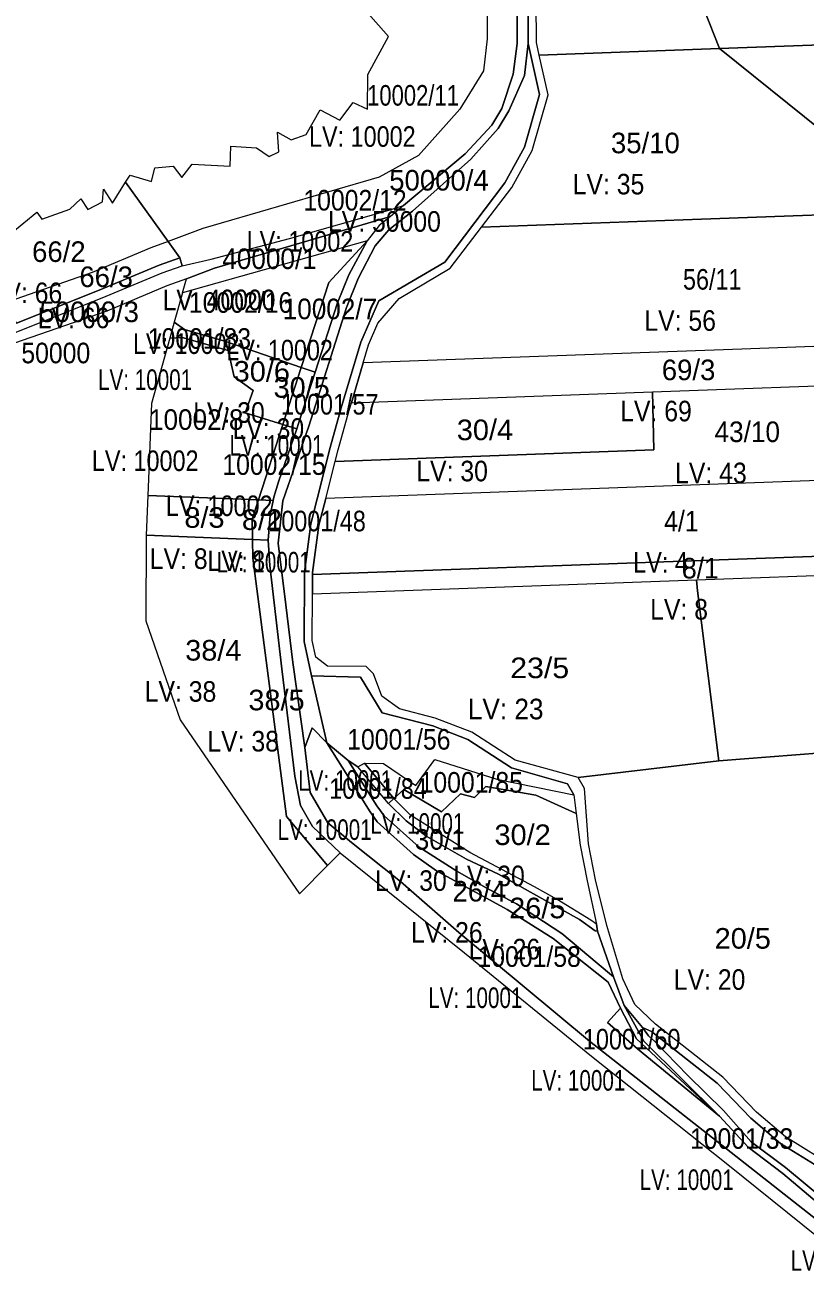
# Model space of a CAD drawing. Extents: x -713758 to -711119, y -1123067 to -1120789.
# Drawn here: x -713169 to -712790, y -1122550 to -1121945 of the extents above; entities that cross this region are included whole.
import ezdxf
from ezdxf.enums import TextEntityAlignment as Align

# ---------------------------------------------------------------- set-up
doc = ezdxf.new("R2010")
doc.units = 0
doc.header["$LTSCALE"] = 4
doc.layers.add('10', color=7, linetype='Continuous', lineweight=13)
doc.layers.add('11', color=7, linetype='Continuous')
doc.layers.add('13', color=7, linetype='Continuous')

msp = doc.modelspace()

# ---------------------------------------------------------------- linework, layer by layer
at = {"layer": '10'}
for points in [[(-712944.91, -1121832.77), (-712944, -1121951.73), (-712945.8, -1121967.3), (-712957.4, -1121986.04), (-712977.36, -1122008.49), (-712996.6, -1122018.99), (-713045.48, -1122033.25), (-713082.19, -1122044), (-713099.09, -1122050.28), (-713119.7, -1122021.46), (-713117.55, -1122018), (-713107.1, -1122021.15), (-713105.44, -1122014.52), (-713096.64, -1122013.69), (-713092.33, -1122019.16), (-713087.35, -1122012.69), (-713068.94, -1122013.69), (-713068.61, -1122003.9), (-713056.16, -1122004.73), (-713050.03, -1122009.04), (-713045.22, -1122006.72), (-713045.88, -1121997.1), (-713039.36, -1122000.91), (-713031.99, -1121998.26), (-713025.14, -1121986.31), (-713015.68, -1121991.29), (-713009.21, -1121982.66), (-713002.25, -1121985.98), (-713002.08, -1121969.06), (-712991.96, -1121950.64), (-713003.08, -1121938.2)], [(-712929.21, -1121894.95), (-712929.46, -1121954.09), (-712931.35, -1121968.92), (-712936.86, -1121985.6), (-712941.79, -1121993.69), (-712954.71, -1122007.7), (-712984.65, -1122032.69), (-712991, -1122038.19), (-712996.49, -1122042.47), (-713002.32, -1122049.96), (-713011.31, -1122066.5), (-713016.78, -1122080.08), (-713027.64, -1122113.79), (-713035.65, -1122138.64), (-713036.53, -1122141.22), (-713045.38, -1122167.06), (-713047.67, -1122174.42), (-713048.02, -1122176.08), (-713049.5, -1122183.21), (-713050.51, -1122195.35), (-713049.59, -1122207.7), (-713043.87, -1122257.93), (-713037.46, -1122309.99), (-713034.78, -1122324.24), (-713028.91, -1122334.48), (-713015.4, -1122347.26), (-712955.02, -1122395.77), (-712893.31, -1122446.1), (-712827.18, -1122498.66), (-712776.53, -1122539.37)], [(-712772.56, -1122534.45), (-712894.29, -1122438.71), (-712957.76, -1122385.97), (-712986.1, -1122361.18), (-713010.04, -1122342.27), (-713021.42, -1122332.63), (-713029.98, -1122317.89), (-713032.71, -1122296.02), (-713038.55, -1122254.75), (-713041.88, -1122226.75), (-713045.67, -1122196.79), (-713043.32, -1122176.31), (-713030.64, -1122139.91), (-713012.41, -1122082.34), (-713006.74, -1122068.22), (-712998.53, -1122052.43), (-712991.77, -1122044.64), (-712980.32, -1122035.6), (-712951.96, -1122010.31), (-712938.67, -1121995.31), (-712933.46, -1121986.71), (-712925.93, -1121969.6), (-712924.13, -1121954.03), (-712924.19, -1121934.01)], [(-712924.19, -1121934.01), (-712924.13, -1121954.03), (-712918.57, -1121978.84), (-712925.98, -1122004.5), (-712935.4, -1122021.81), (-712964.66, -1122060.23), (-712996.72, -1122079.08), (-713005.42, -1122099.09), (-713014.94, -1122131.09), (-713020.31, -1122150.38), (-713029.69, -1122187.36), (-713032.85, -1122210.83), (-713033.03, -1122244.52)], [(-712774.62, -1122500.39), (-712799.12, -1122485.22), (-712813.16, -1122473.21), (-712829.61, -1122456.21), (-712862.21, -1122430.51), (-712872.38, -1122420.97), (-712878.07, -1122408.41), (-712885.9, -1122382.52), (-712891.47, -1122360.38), (-712894.85, -1122342.83), (-712896.75, -1122315.98), (-712899.9, -1122310.71), (-712930.52, -1122302.24), (-712951.57, -1122288.64), (-712969.26, -1122281.82), (-712986.71, -1122277.24), (-712995.2, -1122271.13), (-712999.26, -1122260.23), (-713002.77, -1122256.8), (-713021.65, -1122256.64), (-713027.24, -1122252.26), (-713029.03, -1122244.1), (-713028.91, -1122221.35), (-713028.86, -1122212.11), (-713028.85, -1122211.11), (-713025.76, -1122188.12), (-713022.45, -1122175.1), (-713017.89, -1122157.12), (-713016.44, -1122151.41), (-713011.1, -1122132.22), (-713010.04, -1122128.66), (-713004.26, -1122109.23), (-713001.65, -1122100.46), (-712997.1, -1122089.99), (-712986.87, -1122077.93), (-712961.95, -1122063.28), (-712946.78, -1122043.35), (-712932.04, -1122023.99), (-712922.26, -1122006.03), (-712914.44, -1121978.97), (-712918.75, -1121959.74), (-712920.13, -1121953.58), (-712920.19, -1121933.95)], [(-713179.85, -1122097.09), (-713131.11, -1122077.56), (-713102.01, -1122065.46), (-713092.2, -1122062.07), (-713078.09, -1122058.85), (-713040.02, -1122048.87), (-712992.26, -1122035.27), (-712984.65, -1122032.69), (-712991, -1122038.19), (-713039.52, -1122052.34), (-713076.57, -1122063.19), (-713090.12, -1122068.35), (-713099.67, -1122071.82), (-713128.83, -1122084.07), (-713177.94, -1122101.13)], [(-713179.85, -1122097.09), (-713131.11, -1122077.56), (-713102.01, -1122065.46), (-713092.2, -1122062.07), (-713093.3, -1122058.22), (-713103.43, -1122061.72), (-713132.6, -1122073.85), (-713172.8, -1122089.95)], [(-713033.03, -1122244.52), (-713029.35, -1122261.3), (-713005.54, -1122261.94), (-712995.14, -1122279.16), (-712970.49, -1122285.63), (-712953.4, -1122292.22), (-712932.2, -1122305.92), (-712905.05, -1122313.79), (-712901.9, -1122319.06), (-712900.74, -1122328.21), (-712898.8, -1122343.47), (-712895.46, -1122360.8), (-712890.97, -1122381.84), (-712890.37, -1122385.34), (-712882.72, -1122407.47), (-712877.48, -1122421.44), (-712868.55, -1122432.16), (-712864.27, -1122433.98), (-712832.3, -1122459.19), (-712815.9, -1122476.13), (-712801.49, -1122488.46), (-712776.27, -1122504.07)], [(-712782.82, -1122518), (-712800.46, -1122503.04), (-712817.28, -1122490.23), (-712831.24, -1122475.24), (-712870.99, -1122442.45), (-712885.59, -1122429.63), (-712879.25, -1122422.78), (-712885.31, -1122410.06), (-712911.93, -1122388.85), (-712934.36, -1122374.71), (-712947.93, -1122367.31), (-712968.65, -1122355.94), (-712979.85, -1122348.12), (-712997.42, -1122332.12), (-713001.17, -1122326.78), (-713009.01, -1122314.38), (-713022.03, -1122293.87), (-713029.08, -1122286.58), (-713032.71, -1122296.02), (-713029.98, -1122317.89), (-713021.42, -1122332.63), (-713010.04, -1122342.27), (-712986.1, -1122361.18), (-712957.76, -1122385.97), (-712894.29, -1122438.71), (-712772.56, -1122534.45)], [(-712776.27, -1122504.07), (-712801.49, -1122488.46), (-712815.9, -1122476.13), (-712832.3, -1122459.19), (-712864.27, -1122433.98), (-712868.55, -1122432.16), (-712865.73, -1122436.15), (-712862.65, -1122438.97), (-712846.59, -1122455.35), (-712829.18, -1122472.48), (-712815.86, -1122487.57), (-712799.18, -1122500.14), (-712780.93, -1122515.2)]]:
    msp.add_lwpolyline(points, dxfattribs=at)
for points in [[(-713099.09, -1122050.28), (-713093.3, -1122058.22), (-713092.2, -1122062.07), (-713078.09, -1122058.85), (-713040.02, -1122048.87), (-712992.26, -1122035.27), (-712984.65, -1122032.69), (-712954.71, -1122007.7), (-712941.79, -1121993.69), (-712936.86, -1121985.6), (-712931.35, -1121968.92), (-712929.46, -1121954.09), (-712929.21, -1121894.95), (-712929.12, -1121844.01), (-712939.8, -1121834.06), (-712944.91, -1121832.77), (-712944, -1121951.73), (-712945.8, -1121967.3), (-712957.4, -1121986.04), (-712977.36, -1122008.49), (-712996.6, -1122018.99), (-713045.48, -1122033.25), (-713082.19, -1122044)], [(-712870.42, -1121857.05), (-712700.85, -1121850.86), (-712698.93, -1121864.01), (-712694.13, -1121895.03), (-712687.55, -1121951.31), (-712831.1, -1121956.54)], [(-712920.74, -1121858.89), (-712870.42, -1121857.05), (-712831.1, -1121956.54), (-712918.75, -1121959.74), (-712920.13, -1121953.58), (-712920.19, -1121933.95), (-712920.62, -1121894.76)], [(-713045.67, -1122196.79), (-713041.88, -1122226.75), (-713038.55, -1122254.75), (-713032.71, -1122296.02), (-713029.08, -1122286.58), (-713022.03, -1122293.87), (-713029.35, -1122261.3), (-713033.03, -1122244.52), (-713032.85, -1122210.83), (-713029.69, -1122187.36), (-713020.31, -1122150.38), (-713014.94, -1122131.09), (-713005.42, -1122099.09), (-712996.72, -1122079.08), (-712964.66, -1122060.23), (-712935.4, -1122021.81), (-712925.98, -1122004.5), (-712918.57, -1121978.84), (-712924.13, -1121954.03), (-712925.93, -1121969.6), (-712933.46, -1121986.71), (-712938.67, -1121995.31), (-712951.96, -1122010.31), (-712980.32, -1122035.6), (-712991.77, -1122044.64), (-712998.53, -1122052.43), (-713006.74, -1122068.22), (-713012.41, -1122082.34), (-713030.64, -1122139.91), (-713043.32, -1122176.31)], [(-712831.1, -1121956.54), (-712687.55, -1121951.31), (-712686.83, -1121957.49), (-712682.74, -1121995.84), (-712678.59, -1122015.49), (-712672.75, -1122031.36), (-712671.57, -1122033.31), (-712732.93, -1122035.55)], [(-712946.78, -1122043.35), (-712932.04, -1122023.99), (-712922.26, -1122006.03), (-712914.44, -1121978.97), (-712918.75, -1121959.74), (-712831.1, -1121956.54), (-712732.93, -1122035.55), (-712839.85, -1122039.45)], [(-713200.85, -1122053.94), (-713175.48, -1122046.35), (-713162.84, -1122036.08), (-713160.35, -1122039.4), (-713146.75, -1122034.59), (-713141.44, -1122029.61), (-713138.12, -1122034.76), (-713130.99, -1122030.94), (-713130.49, -1122024.8), (-713126.01, -1122031.6), (-713119.7, -1122021.46), (-713099.09, -1122050.28), (-713107.42, -1122053.38), (-713135.98, -1122065.38), (-713179.96, -1122080.66)], [(-713004.26, -1122109.23), (-713001.65, -1122100.46), (-712997.1, -1122089.99), (-712986.87, -1122077.93), (-712961.95, -1122063.28), (-712946.78, -1122043.35), (-712839.85, -1122039.45), (-712732.93, -1122035.55), (-712671.57, -1122033.31), (-712648.66, -1122071.25), (-712639.54, -1122087.86), (-712636.58, -1122094.53), (-712636.27, -1122095.8), (-712820.27, -1122102.52)], [(-713092.03, -1122075.13), (-713090.12, -1122068.35), (-713076.57, -1122063.19), (-713039.52, -1122052.34), (-712991, -1122038.19), (-712996.49, -1122042.47), (-713002.32, -1122049.96)], [(-713179.96, -1122080.66), (-713172.8, -1122089.95), (-713132.6, -1122073.85), (-713103.43, -1122061.72), (-713093.3, -1122058.22), (-713099.09, -1122050.28), (-713107.42, -1122053.38), (-713135.98, -1122065.38)], [(-713096.05, -1122089.47), (-713091.11, -1122093.06), (-713070.96, -1122098.76), (-713034.39, -1122111.45), (-713021.01, -1122070.15), (-713002.32, -1122049.96), (-713092.03, -1122075.13)], [(-713034.39, -1122111.45), (-713027.64, -1122113.79), (-713016.78, -1122080.08), (-713011.31, -1122066.5), (-713002.32, -1122049.96), (-713021.01, -1122070.15)], [(-713098.24, -1122097.26), (-713092.17, -1122096.94), (-713069.91, -1122103.22), (-713070.96, -1122098.76), (-713091.11, -1122093.06), (-713096.05, -1122089.47)], [(-713108.98, -1122173.65), (-713055.22, -1122175.79), (-713043.34, -1122139.11), (-713061.64, -1122133.42), (-713057.69, -1122122.67), (-713066.9, -1122115.95), (-713069.91, -1122103.22), (-713092.17, -1122096.94), (-713098.24, -1122097.26), (-713107.15, -1122128.96)], [(-713070.96, -1122098.76), (-713069.91, -1122103.22), (-713066.9, -1122115.95), (-713057.69, -1122122.67), (-713061.64, -1122133.42), (-713043.34, -1122139.11), (-713034.39, -1122111.45)], [(-713010.04, -1122128.66), (-712863.78, -1122123.32), (-712748.22, -1122119.11), (-712632.65, -1122114.89), (-712632.85, -1122109.87), (-712636.27, -1122095.8), (-712820.27, -1122102.52), (-713004.26, -1122109.23)], [(-713043.34, -1122139.11), (-713036.53, -1122141.22), (-713035.65, -1122138.64), (-713027.64, -1122113.79), (-713034.39, -1122111.45)], [(-713022.45, -1122175.1), (-713017.89, -1122157.12), (-712863.04, -1122151.46), (-712863.78, -1122123.32), (-712748.22, -1122119.11), (-712632.65, -1122114.89), (-712632.44, -1122120.31), (-712636.42, -1122143.91), (-712641.22, -1122161.19), (-712831.84, -1122168.14)], [(-713017.89, -1122157.12), (-713016.44, -1122151.41), (-713011.1, -1122132.22), (-713010.04, -1122128.66), (-712863.78, -1122123.32), (-712863.04, -1122151.46)], [(-713055.22, -1122175.79), (-713048.02, -1122176.08), (-713047.67, -1122174.42), (-713045.38, -1122167.06), (-713036.53, -1122141.22), (-713043.34, -1122139.11)], [(-713028.86, -1122212.11), (-712840.29, -1122205.23), (-712651.72, -1122198.35), (-712648.29, -1122186.66), (-712641.22, -1122161.19), (-712831.84, -1122168.14), (-713022.45, -1122175.1), (-713025.76, -1122188.12), (-713028.85, -1122211.11)], [(-713109.77, -1122192.99), (-713058.1, -1122195.05), (-713058.24, -1122185.1), (-713055.22, -1122175.79), (-713108.98, -1122173.65)], [(-713058.24, -1122185.1), (-713058.1, -1122195.05), (-713050.51, -1122195.35), (-713049.5, -1122183.21), (-713048.02, -1122176.08), (-713055.22, -1122175.79)], [(-713109.96, -1122234.59), (-713093.16, -1122282.68), (-713035.23, -1122367.19), (-713021.59, -1122353.48), (-713041.62, -1122329.55), (-713057.98, -1122204.02), (-713058.1, -1122195.05), (-713109.77, -1122192.99)], [(-713058.1, -1122195.05), (-713057.98, -1122204.02), (-713041.62, -1122329.55), (-713021.59, -1122353.48), (-713015.4, -1122347.26), (-713028.91, -1122334.48), (-713034.78, -1122324.24), (-713037.46, -1122309.99), (-713043.87, -1122257.93), (-713049.59, -1122207.7), (-713050.51, -1122195.35)], [(-713028.91, -1122221.35), (-712842.39, -1122214.55), (-712682.59, -1122208.72), (-712654.45, -1122207.69), (-712651.72, -1122198.35), (-712840.29, -1122205.23), (-713028.86, -1122212.11)], [(-712842.39, -1122214.55), (-712682.59, -1122208.72), (-712654.45, -1122207.69), (-712660.03, -1122226.71), (-712660.27, -1122244.45), (-712657.62, -1122253.69), (-712650.61, -1122267.8), (-712637.62, -1122283.48), (-712781.58, -1122298.68), (-712831.54, -1122302.56), (-712841.94, -1122220.03)], [(-713029.03, -1122244.1), (-713028.91, -1122221.35), (-712842.39, -1122214.55), (-712841.94, -1122220.03), (-712831.54, -1122302.56), (-712899.9, -1122310.71), (-712930.52, -1122302.24), (-712951.57, -1122288.64), (-712969.26, -1122281.82), (-712986.71, -1122277.24), (-712995.2, -1122271.13), (-712999.26, -1122260.23), (-713002.77, -1122256.8), (-713021.65, -1122256.64), (-713027.24, -1122252.26)], [(-713029.35, -1122261.3), (-713022.03, -1122293.87), (-713011.56, -1122302.38), (-713006.84, -1122305.48), (-713003.73, -1122303.73), (-712994.41, -1122303.86), (-712978.78, -1122314.61), (-712969.51, -1122301.85), (-712939.28, -1122311.38), (-712901.9, -1122319.06), (-712905.05, -1122313.79), (-712932.2, -1122305.92), (-712953.4, -1122292.22), (-712970.49, -1122285.63), (-712995.14, -1122279.16), (-713005.54, -1122261.94)], [(-713022.03, -1122293.87), (-713009.01, -1122314.38), (-713001.17, -1122326.78), (-712997.42, -1122332.12), (-712979.85, -1122348.12), (-712968.65, -1122355.94), (-712947.93, -1122367.31), (-712934.36, -1122374.71), (-712911.93, -1122388.85), (-712885.31, -1122410.06), (-712879.25, -1122422.78), (-712871.46, -1122437.62), (-712831.24, -1122475.24), (-712867.93, -1122438.67), (-712877.48, -1122421.44), (-712882.72, -1122407.47), (-712890.53, -1122400.9), (-712907.83, -1122386.4), (-712929.83, -1122371.95), (-712944.47, -1122364.21), (-712958.72, -1122356.09), (-712977.09, -1122344.54), (-712994.17, -1122329.26), (-712997.59, -1122324.4), (-713011.56, -1122302.38)], [(-712899.9, -1122310.71), (-712831.54, -1122302.56), (-712781.58, -1122298.68), (-712767.93, -1122326.7), (-712748.89, -1122353.98), (-712703.17, -1122396.9), (-712695.91, -1122402.6), (-712774.62, -1122500.39), (-712799.12, -1122485.22), (-712813.16, -1122473.21), (-712829.61, -1122456.21), (-712862.21, -1122430.51), (-712872.38, -1122420.97), (-712878.07, -1122408.41), (-712885.9, -1122382.52), (-712891.47, -1122360.38), (-712894.85, -1122342.83), (-712896.75, -1122315.98)], [(-713011.56, -1122302.38), (-712997.59, -1122324.4), (-712994.17, -1122329.26), (-712977.09, -1122344.54), (-712958.72, -1122356.09), (-712944.47, -1122364.21), (-712929.83, -1122371.95), (-712907.83, -1122386.4), (-712890.53, -1122400.9), (-712882.72, -1122407.47), (-712890.37, -1122385.34), (-712891.54, -1122385.07), (-712899.12, -1122379.7), (-712922.96, -1122366.41), (-712938.5, -1122357.67), (-712954.07, -1122350.27), (-712973.3, -1122339.3), (-712983.48, -1122331.74), (-712992, -1122323.28), (-713006.84, -1122305.48)], [(-713006.84, -1122305.48), (-713003.73, -1122303.73), (-712989.41, -1122320.92), (-712992, -1122323.28)], [(-713003.73, -1122303.73), (-712994.41, -1122303.86), (-712978.78, -1122314.61), (-712969.51, -1122301.85), (-712939.28, -1122311.38), (-712901.9, -1122319.06), (-712900.74, -1122328.21), (-712920.36, -1122319.31), (-712944.68, -1122315.1), (-712950.2, -1122320.39), (-712957.07, -1122318.58), (-712966.19, -1122327.34), (-712984.6, -1122316.5), (-712989.41, -1122320.92)], [(-712989.41, -1122320.92), (-712984.6, -1122316.5), (-712966.19, -1122327.34), (-712957.07, -1122318.58), (-712950.2, -1122320.39), (-712944.68, -1122315.1), (-712920.36, -1122319.31), (-712900.74, -1122328.21), (-712898.8, -1122343.47), (-712895.46, -1122360.8), (-712890.97, -1122381.84), (-712893.62, -1122379.92), (-712910.08, -1122369.89), (-712921.12, -1122363.7), (-712952.47, -1122347.02), (-712981.3, -1122328.98)], [(-712989.41, -1122320.92), (-712992, -1122323.28), (-712983.48, -1122331.74), (-712973.3, -1122339.3), (-712954.07, -1122350.27), (-712938.5, -1122357.67), (-712922.96, -1122366.41), (-712899.12, -1122379.7), (-712891.54, -1122385.07), (-712890.37, -1122385.34), (-712890.97, -1122381.84), (-712893.62, -1122379.92), (-712910.08, -1122369.89), (-712921.12, -1122363.7), (-712952.47, -1122347.02), (-712981.3, -1122328.98)], [(-712877.48, -1122421.44), (-712867.93, -1122438.67), (-712831.24, -1122475.24), (-712817.28, -1122490.23), (-712800.46, -1122503.04), (-712782.82, -1122518), (-712773.42, -1122532.7), (-712772.56, -1122534.45), (-712768.79, -1122532.19), (-712771.43, -1122529.55), (-712780.93, -1122515.2), (-712799.18, -1122500.14), (-712815.86, -1122487.57), (-712829.18, -1122472.48), (-712846.59, -1122455.35), (-712862.65, -1122438.97), (-712865.73, -1122436.15), (-712868.55, -1122432.16)], [(-712885.59, -1122429.63), (-712870.99, -1122442.45), (-712831.24, -1122475.24), (-712871.46, -1122437.62), (-712879.25, -1122422.78)]]:
    msp.add_lwpolyline(points, close=True, dxfattribs=at)

# ---------------------------------------------------------------- texts
at = {"layer": '11'}
for s, width, p in [('10002/11', 0.8, (-712980.08, -1121984.26)), ('10002/12', 0.9, (-713008.26, -1122035.21)), ('40000/1', 0.95, (-713049.8, -1122063.64)), ('56/11', 0.85, (-712834.701, -1122073.64)), ('10002/16', 0.9, (-713063.86, -1122084.89)), ('10002/7', 0.95, (-713020.44, -1122088.02)), ('10001/83', 0.9, (-713083.86, -1122102.39)), ('30/6', 1.05, (-713053.55, -1122118.33)), ('30/5', 1.05, (-713034.179, -1122126.14)), ('10001/57', 0.85, (-713020.53, -1122134.33)), ('10002/8', 0.95, (-713085.419, -1122141.77)), ('30/4', 1.05, (-712945.14, -1122146.77)), ('43/10', 0.95, (-712817.68, -1122147.7)), ('10002/15', 0.9, (-713047.62, -1122163.64)), ('8/3', 1.05, (-713081.4, -1122189.33)), ('8/2', 1.05, (-713053.47, -1122190.38)), ('10001/48', 0.85, (-713026.709, -1122191.06)), ('4/1', 0.9, (-712849.699, -1122191.14)), ('8/1', 0.95, (-712840.48, -1122213.95)), ('38/4', 1.05, (-713077.09, -1122253.85)), ('23/5', 1.1, (-712918.53, -1122262.38)), ('38/5', 1.05, (-713046.4, -1122278.02)), ('10001/56', 0.9, (-712986.96, -1122297.11)), ('10001/84', 0.85, (-712997.081, -1122320.98)), ('10001/85', 0.9, (-712951.78, -1122318.01)), ('30/1', 0.95, (-712966.87, -1122345.73)), ('30/2', 1.05, (-712926.83, -1122343.46)), ('26/5', 1.05, (-712919.701, -1122379.04)), ('20/5', 1.05, (-712819.88, -1122393.8)), ('10001/58', 0.9, (-712923.65, -1122402.64)), ('10001/60', 0.85, (-712873.841, -1122442.78)), ('10001/33', 0.9, (-712820.42, -1122491.04))]:
    msp.add_text(s, height=10, dxfattribs=dict(at, width=width)).set_placement(p, align=Align.CENTER)
for s, p in [('35/10', (-712867.189, -1122007.39)), ('50000/4', (-712967.47, -1122025.51)), ('66/2', (-713152.14, -1122060.2)), ('66/3', (-713129.17, -1122072.39)), ('50000/3', (-713137.41, -1122089.42)), ('69/3', (-712846.2, -1122117.63)), ('26/4', (-712947.89, -1122370.9))]:
    msp.add_text(s, height=10, dxfattribs=at).set_placement(p, align=Align.CENTER)
at = {"layer": '13'}
for s, width, p in [('LV: 10002 ', 0.85, (-713003.134, -1122004.26)), ('LV: 35 ', 0.9, (-712883.417, -1122027.39)), ('LV: 50000 ', 0.9, (-712992.298, -1122045.51)), ('LV: 10002 ', 0.85, (-713033.422, -1122055.21)), ('LV: 66 ', 0.9, (-713166.226, -1122080.2)), ('LV: 40000 ', 0.9, (-713072.652, -1122083.64)), ('LV: 66 ', 0.9, (-713143.324, -1122092.39)), ('LV: 56 ', 0.9, (-712848.62, -1122093.64)), ('LV: 10002 ', 0.85, (-713088.654, -1122104.89)), ('LV: 50000 ', 0.9, (-713162.673, -1122109.42)), ('LV: 10002 ', 0.85, (-713043.327, -1122108.02)), ('LV: 10001 ', 0.75, (-713108.855, -1122122.39)), ('LV: 30 ', 0.9, (-713067.838, -1122138.33)), ('LV: 69 ', 0.9, (-712860.353, -1122137.63)), ('LV: 30 ', 0.9, (-713048.702, -1122146.14)), ('LV: 10001 ', 0.75, (-713044.99, -1122154.33)), ('LV: 10002 ', 0.85, (-713108.608, -1122161.77)), ('LV: 30 ', 0.9, (-712959.428, -1122166.77)), ('LV: 43 ', 0.9, (-712833.674, -1122167.7)), ('LV: 10002 ', 0.85, (-713072.648, -1122183.64)), ('LV: 8 ', 0.9, (-713092.243, -1122209.33)), ('LV: 8 ', 0.9, (-713064.245, -1122210.38)), ('LV: 10001 ', 0.75, (-713051.236, -1122211.06)), ('LV: 4 ', 0.85, (-712858.232, -1122211.14)), ('LV: 8 ', 0.9, (-712849.147, -1122233.95)), ('LV: 38 ', 0.9, (-713091.378, -1122273.85)), ('LV: 23 ', 0.95, (-712933.287, -1122282.38)), ('LV: 38 ', 0.9, (-713060.922, -1122298.02)), ('LV: 10001 ', 0.75, (-713011.62, -1122317.11)), ('LV: 10001 ', 0.75, (-713021.64, -1122340.98)), ('LV: 10001 ', 0.75, (-712976.574, -1122338.01)), ('LV: 30 ', 0.9, (-712941.486, -1122363.46)), ('LV: 30 ', 0.9, (-712979.418, -1122365.73)), ('LV: 26 ', 0.9, (-712961.977, -1122390.9)), ('LV: 26 ', 0.9, (-712934.022, -1122399.04)), ('LV: 20 ', 0.9, (-712834.336, -1122413.8)), ('LV: 10001 ', 0.75, (-712948.411, -1122422.64)), ('LV: 10001 ', 0.75, (-712898.4, -1122462.78)), ('LV: 10001 ', 0.75, (-712845.716, -1122511.04)), ('LV: 10001 ', 0.75, (-712772.35, -1122550.29))]:
    msp.add_text(s, height=10, dxfattribs=dict(at, width=width)).set_placement(p, align=Align.CENTER)

doc.saveas('drawing.dxf')
